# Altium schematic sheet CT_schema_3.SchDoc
size 284 x 172 mm
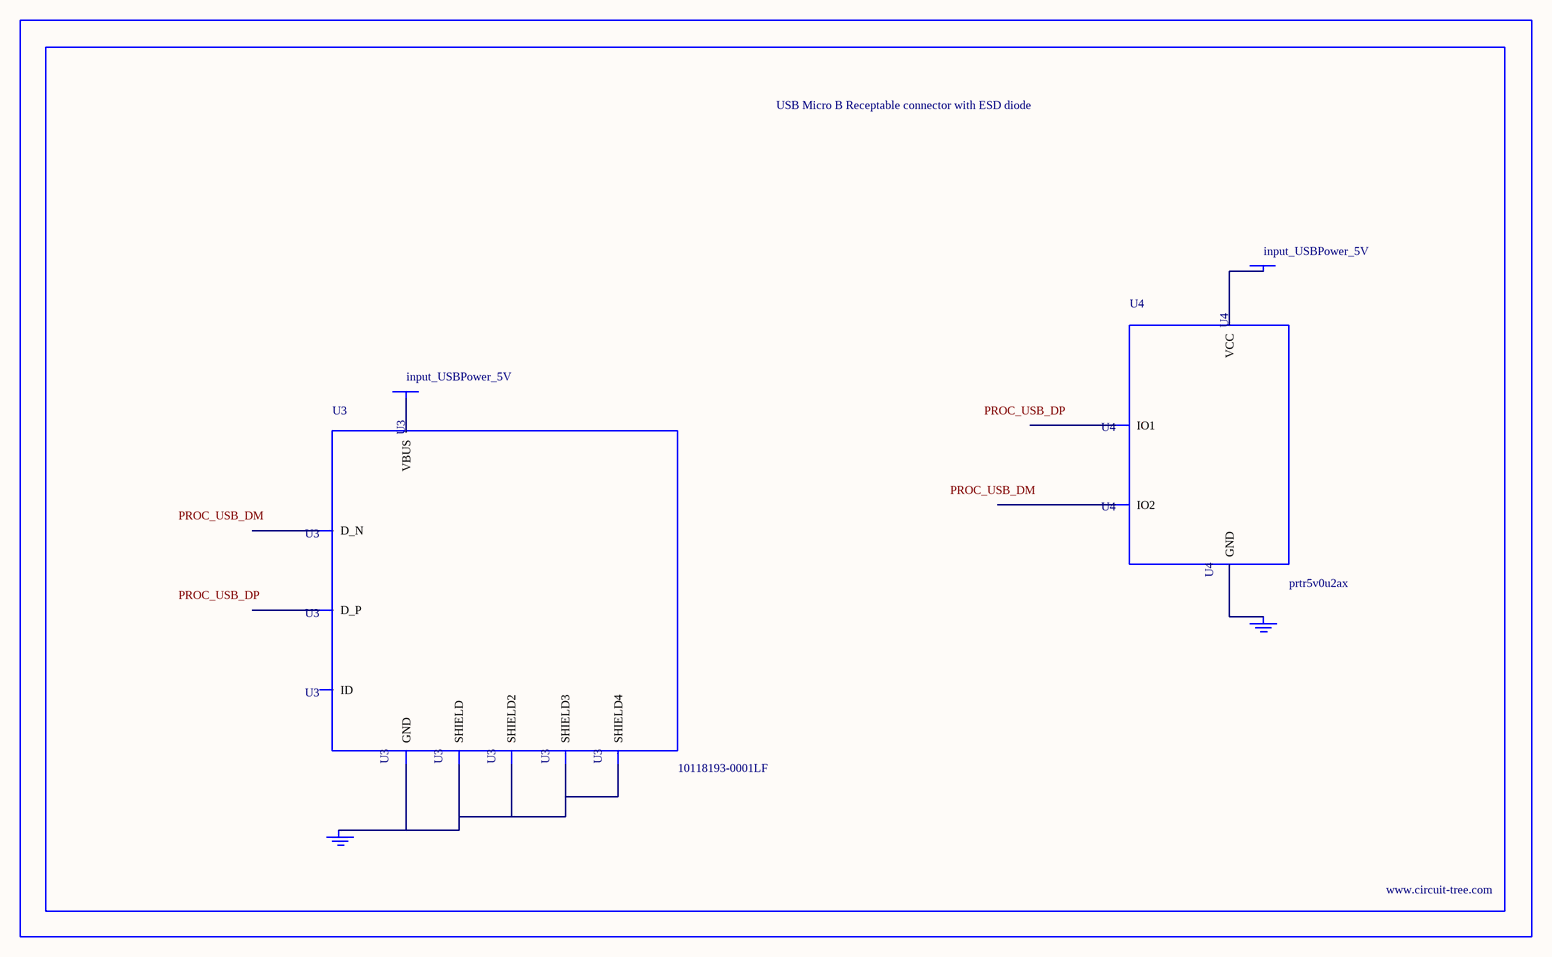
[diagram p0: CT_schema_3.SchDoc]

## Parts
BORDER2  (no value)
GND_INSTANCE_2_0  (no value)
GND_INSTANCE_2_1  (no value)
POWER_INSTANCE_2_0  input_USBPower_5V
POWER_INSTANCE_2_1  input_USBPower_5V
U3  10118193-0001LF  [FCI_10118193-0001LF]
U4  prtr5v0u2ax  [SOT143B]

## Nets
NetGND_INSTANCE_2_0_0: GND_INSTANCE_2_0.0(GND) U3.5(GND) U3.6(SHIELD) U3.7(SHIELD2) U3.8(SHIELD3) U3.9(SHIELD4)
NetGND_INSTANCE_2_1_0: GND_INSTANCE_2_1.0(GND) U4.1(GND)
NetPOWER_INSTANCE_2_0_0: POWER_INSTANCE_2_0.0(PWR) U3.1(VBUS)
NetPOWER_INSTANCE_2_1_0: POWER_INSTANCE_2_1.0(PWR) U4.4(VCC)

Not connected (* = marked no-connect by the designer): U3 2(D_N) 3(D_P) 4(ID); U4 2(IO1) 3(IO2)

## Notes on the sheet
- Labels drawn without touching a wire or pin: PROC_USB_DM, PROC_USB_DP

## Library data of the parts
BORDER2 = BORDER_PAGE2
GND_INSTANCE_2_0 GND_INSTANCE_2_1 = GND
POWER_INSTANCE_2_0 POWER_INSTANCE_2_1 = PWR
